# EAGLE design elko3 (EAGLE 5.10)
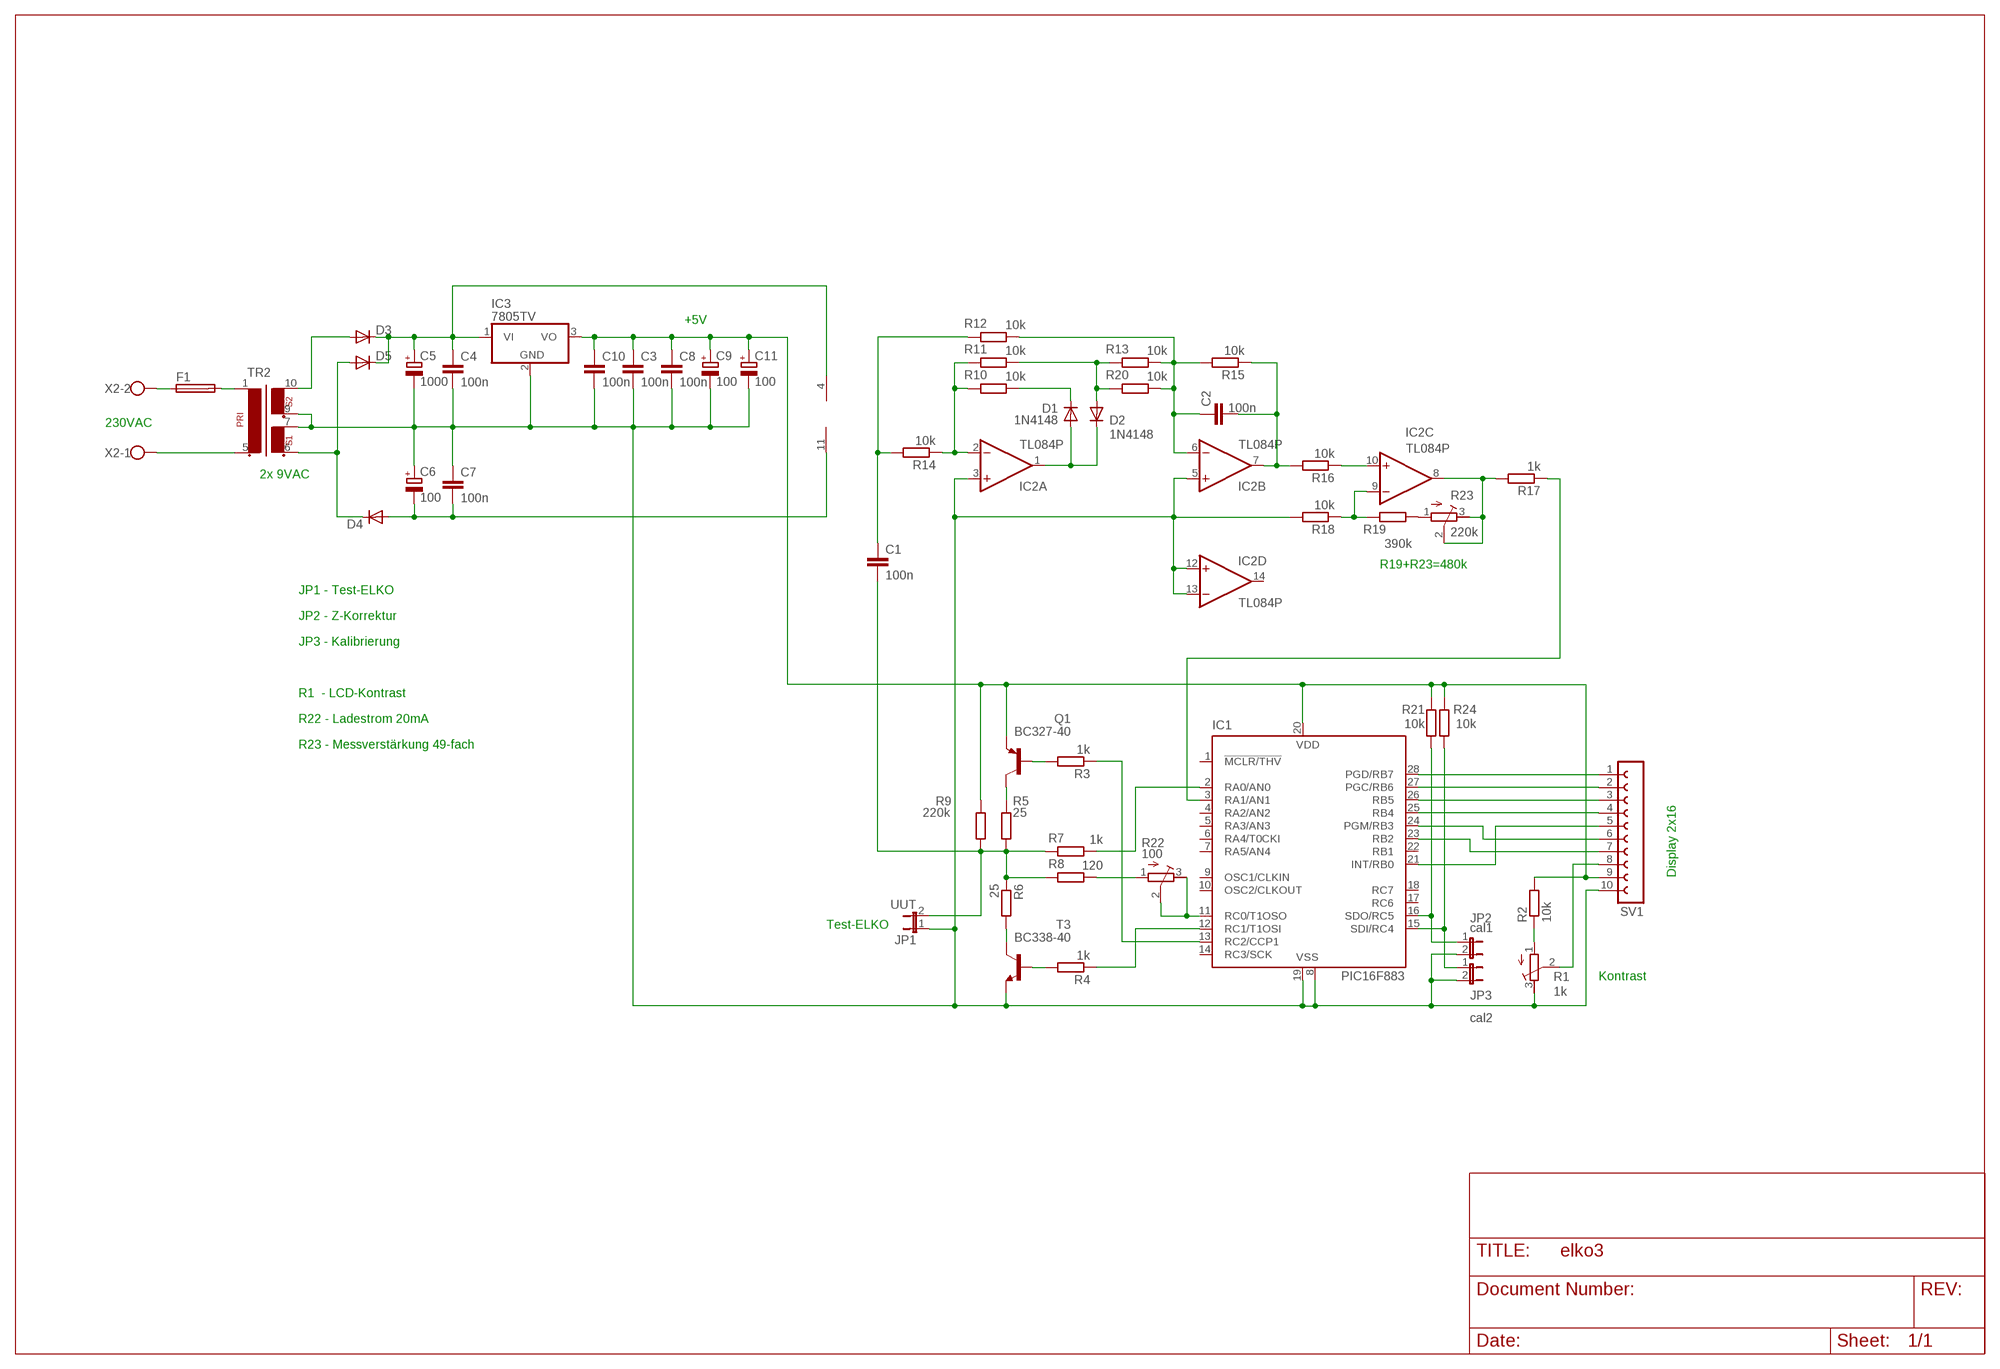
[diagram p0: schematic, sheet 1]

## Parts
C1  100n  C-EU050-025X075  [C050-025X075]
C2  100n  C-EU050-025X075  [C050-025X075]
C3  100n  C-EU050-025X075  [C050-025X075]
C4  100n  C-EU050-025X075  [C050-025X075]
C5  1000  CPOL-EUE5-8.5  [E5-8,5]
C6  100  CPOL-EUE5-6  [E5-6]
C7  100n  C-EU050-025X075  [C050-025X075]
C8  100n  C-EU050-025X075  [C050-025X075]
C9  100  CPOL-EUE5-6  [E5-6]
C10  100n  C-EU050-025X075  [C050-025X075]
C11  100  CPOL-EUE5-6  [E5-6]
D1  1N4148  1N4148DO35-7  [DO35-7]
D2  1N4148  1N4148DO35-7  [DO35-7]
D3  DIODE-DO15-12  [DO15-12]
D4  DIODE-DO15-12  [DO15-12]
D5  DIODE-DO15-12  [DO15-12]
F1  19560  [19560]
IC1  PIC16F883  PIC16873P  [DIL28-3]
IC2  TL084P  [DIL14]
IC3  7805TV  [TO220V]
JP1  UUT  JP1E  [JP1]
JP2  cal1  JP1E  [JP1]
JP3  cal2  JP1E  [JP1]
Q1  BC327-40  [TO92-EBC]
R1  1k  R-TRIMM3339P  [RTRIM3339P]
R2  10k  R-EU_0207/10  [0207/10]
R3  1k  R-EU_0207/10  [0207/10]
R4  1k  R-EU_0207/10  [0207/10]
R5  25  R-EU_0207/10  [0207/10]
R6  25  R-EU_0207/10  [0207/10]
R7  1k  R-EU_0207/10  [0207/10]
R8  120  R-EU_0207/10  [0207/10]
R9  220k  R-EU_0207/10  [0207/10]
R10  10k  R-EU_0207/10  [0207/10]
R11  10k  R-EU_0207/10  [0207/10]
R12  10k  R-EU_0207/10  [0207/10]
R13  10k  R-EU_0207/10  [0207/10]
R14  10k  R-EU_0207/10  [0207/10]
R15  10k  R-EU_0207/10  [0207/10]
R16  10k  R-EU_0207/10  [0207/10]
R17  1k  R-EU_0207/10  [0207/10]
R18  10k  R-EU_0207/10  [0207/10]
R19  390k  R-EU_0207/10  [0207/10]
R20  10k  R-EU_0207/10  [0207/10]
R21  10k  R-EU_0207/10  [0207/10]
R22  100  R-TRIMM64W  [RTRIM64W]
R23  220k  R-TRIMM64W  [RTRIM64W]
R24  10k  R-EU_0207/10  [0207/10]
SV1  FE10-1  [FE10]
T3  BC338-40  NPNBC338-40TO92-EBC  [TO92-EBC]
TR2  VV12  [VV12]
X2  W237-102  [W237-102]

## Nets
N$1: IC1.28(PGD/RB7) SV1.1
N$2: IC1.27(PGC/RB6) SV1.2
N$3: IC1.26(RB5) SV1.3
N$4: IC1.25(RB4) SV1.4
N$5: IC1.21(INT/RB0) SV1.5
N$6: IC1.24(PGM/RB3) SV1.6
N$7: IC1.23(RB2) SV1.7
N$8: R19.1 R23.1(E)
N$9: R8.1 R22.1(E)
N$10: C3.1 C8.1 C9.+ C10.1 C11.+ IC1.20(VDD) IC3.3(VO) Q1.E R2.2 R9.1 R21.2 R24.2 SV1.9
N$11: R1.2(S) SV1.8
N$12: C1.2 JP1.2 R5.2 R6.1 R7.2 R8.2 R9.2
N$13: IC1.2(RA0/AN0) R7.1
N$14: IC1.11(RC0/T1OSO) R22.2(S) R22.3(A)
N$15: Q1.C R5.1
N$16: Q1.B R3.2
N$17: R4.2 T3.B
N$18: IC1.12(RC1/T1OSI) R4.1
N$19: IC1.13(RC2/CCP1) R3.1
N$20: C4.1 C5.+ D3.C D5.C IC2.4(P:V+) IC3.1(VI)
N$21: IC2.2(A:-IN) R10.2 R11.2 R14.1
N$22: D1.A D2.C IC2.1(A:OUT)
N$23: R1.1(E) R2.1
N$24: D1.C R10.1
N$25: D2.A R11.1 R13.2 R20.2
N$26: C1.1 R12.2 R14.2
N$27: C2.1 IC2.6(B:-IN) R12.1 R13.1 R15.2 R20.1
N$28: IC1.16(SDO/RC5) JP2.1 R21.1
N$29: C2.2 IC2.7(B:OUT) R15.1 R16.2
N$30: IC2.10(C:+IN) R16.1
N$31: IC2.8(C:OUT) R17.2 R23.2(S) R23.3(A)
N$32: IC2.9(C:-IN) R18.1 R19.2
N$33: IC1.3(RA1/AN1) R17.1
N$34: R6.2 T3.C
N$35: IC1.15(SDI/RC4) JP3.1 R24.1
N$36: F1.1 X2.2
N$37: C6.- C7.2 D4.A IC2.11(P:V-)
N$38: D4.C D5.A TR2.6
N$39: F1.2 TR2.1
N$40: TR2.5 X2.1
N$41: D3.A TR2.10
VSS: C3.2 C4.2 C5.- C6.+ C7.1 C8.2 C9.- C10.2 C11.- IC1.8(VSS) IC1.19(VSS) IC2.3(A:+IN) IC2.5(B:+IN) IC2.12(D:+IN) IC2.13(D:-IN) IC3.2(GND) JP1.1 JP2.2 JP3.2 R1.3(A) R18.2 SV1.10 T3.E TR2.7 TR2.9
Unconnected: IC1.1(!MCLR/THV) IC1.4(RA2/AN2) IC1.5(RA3/AN3) IC1.6(RA4/T0CKI) IC1.7(RA5/AN4) IC1.9(OSC1/CLKIN) IC1.10(OSC2/CLKOUT) IC1.14(RC3/SCK) IC1.17(RC6) IC1.18(RC7) IC1.22(RB1) IC2.14(D:OUT)

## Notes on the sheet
- +5V
- 230VAC
- 2x 9VAC
- R19+R23=480k
- JP1 - Test-ELKO
- JP2 - Z-Korrektur
- JP3 - Kalibrierung
- R1  - LCD-Kontrast
- R22 - Ladestrom 20mA
- R23 - Messverstärkung 49-fach
- Display 2x16
- Test-ELKO
- Kontrast

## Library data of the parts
C1-C4 C7 C8 C10 = rcl:C-EU: CAPACITOR, European symbol
C5 C6 C9 C11 = rcl:CPOL-EU: POLARIZED CAPACITOR, European symbol
D1 D2 = diode:1N4148: DIODE
D3-D5 = diode:DIODE-: DIODE
F1 = fuse:19560: FUSE HOLDER
IC1 = microchip-6:PIC16*873: MICROCONTROLLER flash type
IC2 = linear:TL084: OP AMP
IC3 = linear:78*: Positive VOLTAGE REGULATOR Source: http://cache.national.com/ds/LM/LM78L05.pdf http://www.fairchildsemi.com/ds/LM/LM7805.pdf
JP1-JP3 = jumper:JP1E: JUMPER
Q1 = transistor-pnp:BC327*: PNP Transistror
R1 R22 R23 = rcl:R-TRIMM: Trimm resistor
R2-R21 R24 = rcl:R-EU_: RESISTOR, European symbol
SV1 = con-lsta:FE10-1: FEMALE HEADER
T3 = sprut:NPN: NPN Transistror
TR2 = trafo:VV12: TRANSFORMER 1 primary winding, 2 secondary windings BLOCK
X2 = con-wago-500:W237-102: WAGO SCREW CLAMP

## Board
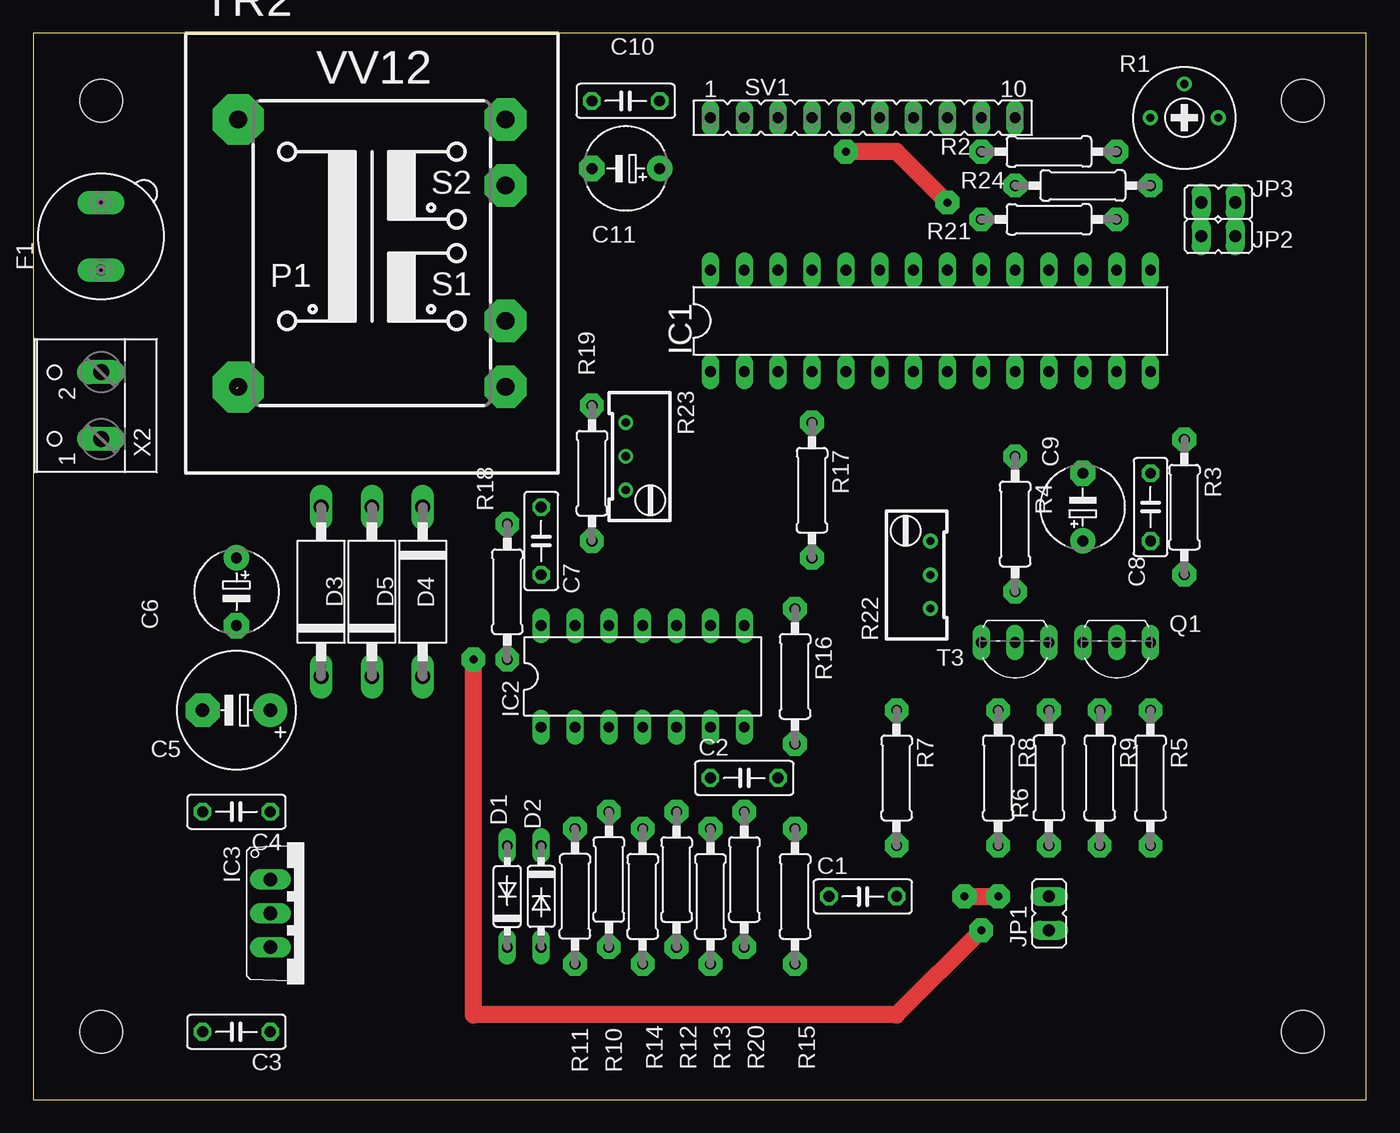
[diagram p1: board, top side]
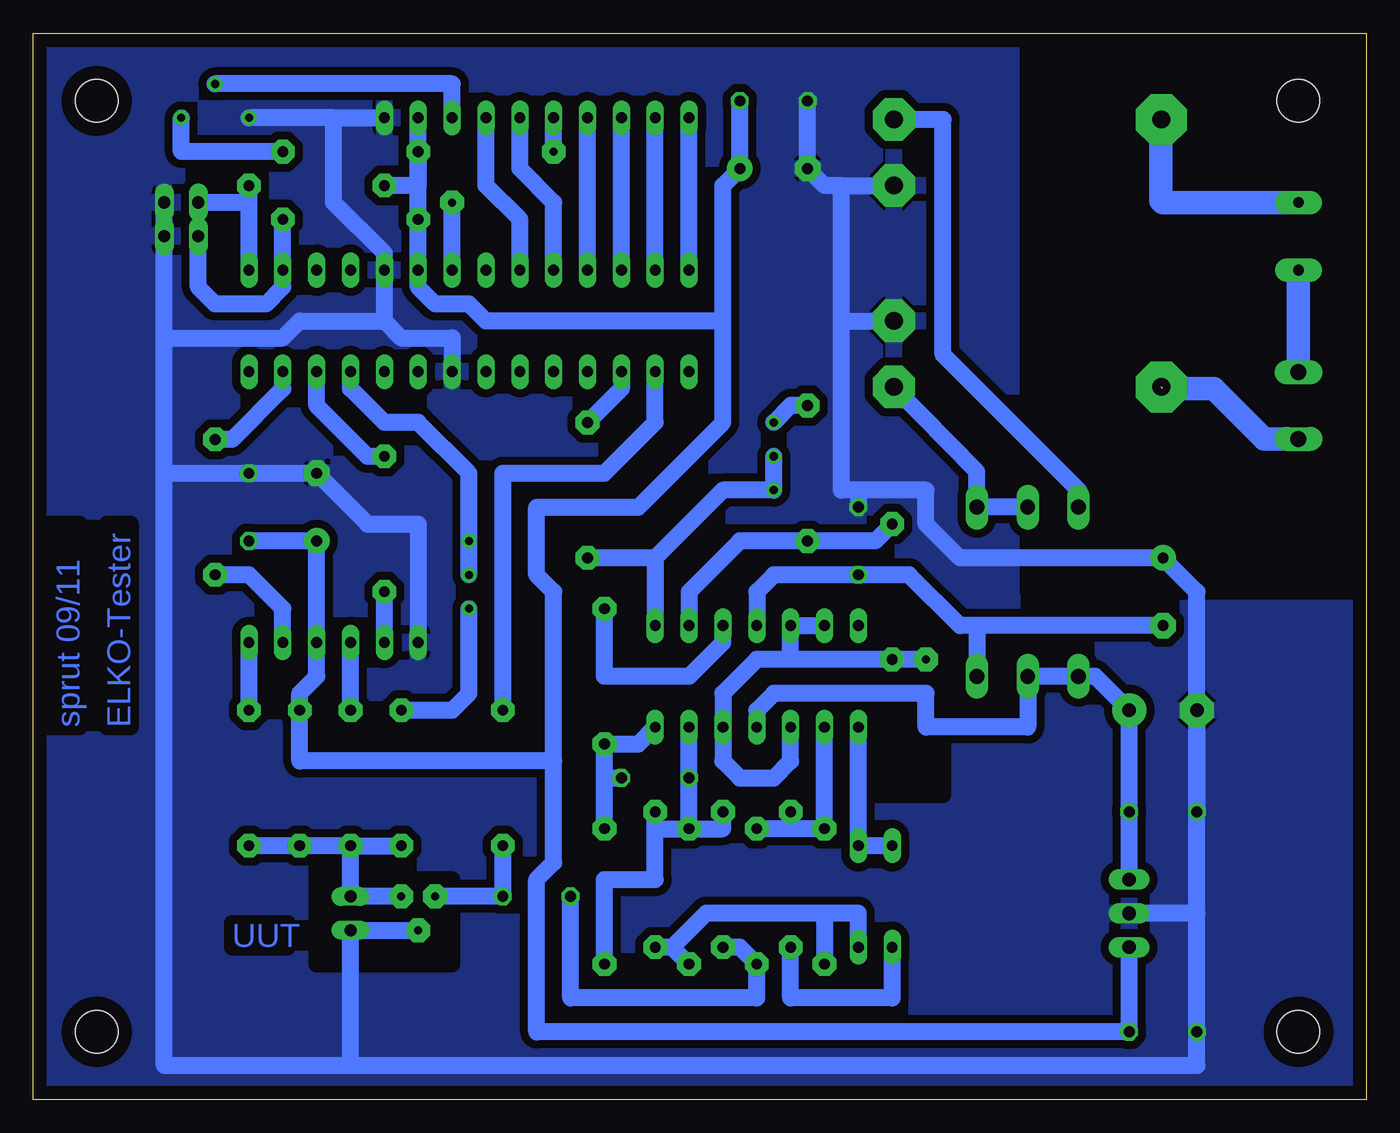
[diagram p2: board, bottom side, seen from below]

Size 100 x 80 mm. Coordinates in mm from the lower left corner, seen from the top.
Outline: 0,0 100,0 100,80 0,80 0,0
Copper layers (1*16): Top 0.035mm / dielectric 1.5mm / Bottom 0.035mm
Design rules "default": minimum track width 10mil, minimum drill 24mil, track to track 8mil, track to pad 8mil, pad to pad 8mil, via to via 8mil, smd to smd 8mil, copper to edge 40mil, drill to drill 8mil, minimum pad ring 10mil, minimum via ring 8mil, stop-mask expansion 4mil, vias tented up to drill 0mil, thermal gap 10mil
Holes 3.2 mm at 5.08,74.93 95.25,74.93 5.08,5.08 95.25,5.08
bRestrict: area 68.6,10.2 to 78.7,16.5; area 31.8,22.9 to 50.8,36.8; area 0,38.1 to 25.4,80

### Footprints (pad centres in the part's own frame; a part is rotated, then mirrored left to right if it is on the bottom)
C050-025X075 = drill 0.813 octagon: 1 -2.54,0; 2 2.54,0
E5-8,5 = drill 1.016 pad 2.54 round: + -2.54,0 | drill 1.016 pad 2.54 octagon: - 2.54,0
E5-6 = drill 0.813 pad 1.905 round: + -2.54,0 | drill 0.813 pad 1.905 octagon: - 2.54,0
DO35-7 = drill 0.813 long: A 3.81,0; C -3.81,0
DO15-12 = drill 1.118 long: A 6.35,0; C -6.35,0
19560 = drill 0.813 pad 1.778 long: 1 -2.54,0; 2 2.54,0
DIL28-3 = drill 0.813 long: 1 -16.51,-3.81; 2 -13.97,-3.81; 3 -11.43,-3.81; 4 -8.89,-3.81; 5 -6.35,-3.81; 6 -3.81,-3.81; 7 -1.27,-3.81; 8 1.27,-3.81; 9 3.81,-3.81; 10 6.35,-3.81; 11 8.89,-3.81; 12 11.43,-3.81; 13 13.97,-3.81; 14 16.51,-3.81; 15 16.51,3.81; 16 13.97,3.81; 17 11.43,3.81; 18 8.89,3.81; 19 6.35,3.81; 20 3.81,3.81; 21 1.27,3.81; 22 -1.27,3.81; 23 -3.81,3.81; 24 -6.35,3.81; 25 -8.89,3.81; 26 -11.43,3.81; 27 -13.97,3.81; 28 -16.51,3.81
DIL14 = drill 0.813 long: 1 -7.62,-3.81; 2 -5.08,-3.81; 3 -2.54,-3.81; 4 0,-3.81; 5 2.54,-3.81; 6 5.08,-3.81; 7 7.62,-3.81; 8 7.62,3.81; 9 5.08,3.81; 10 2.54,3.81; 11 0,3.81; 12 -2.54,3.81; 13 -5.08,3.81; 14 -7.62,3.81
TO220V = drill 1.016 long: 1 -2.54,-2.54; 2 0,-2.54; 3 2.54,-2.54
JP1 = drill 0.914 long: 1 0,-1.27; 2 0,1.27
TO92-EBC = drill 0.813 long: B 0,-1.27; C -2.54,-1.27; E 2.54,-1.27
RTRIM3339P = drill 0.61 round: 1 -2.54,0; 2 0,-2.54; 3 2.54,0
0207/10 = drill 0.813 pad 1.778 octagon: 1 -5.08,0; 2 5.08,0
RTRIM64W = drill 0.61 round: 1 1.27,-2.54; 2 1.27,0; 3 1.27,2.54
FE10 = drill 0.813 long: 1 -11.43,0; 2 -8.89,0; 3 -6.35,0; 4 -3.81,0; 5 -1.27,0; 6 1.27,0; 7 3.81,0; 8 6.35,0; 9 8.89,0; 10 11.43,0
VV12 = drill 1.321 pad 3.81 octagon: 1 -10.033,10.033; 5 -10.033,-10.033 | drill 1.321 pad 3.175 octagon: 6 10.033,-10.033; 7 10.033,-5.08; 9 10.033,5.08; 10 10.033,10.033
W237-102 = drill 1.194 long: 1 -2.5,-1.27; 2 2.5,-1.27

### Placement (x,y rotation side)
C1  62.23,15.24 0 top
C2  53.34,24.13 0 top
C3  15.24,5.08 180 top
C4  15.24,21.59 180 top
C5  15.24,29.21 180 top
C6  15.24,38.1 270 top
C7  38.1,41.91 270 top
C8  83.82,44.45 90 top
C9  78.74,44.45 90 top
C10  44.45,74.93 180 top
C11  44.45,69.85 180 top
D1  35.56,15.24 90 top
D2  38.1,15.24 270 top
D3  21.59,38.1 90 top
D4  29.21,38.1 270 top
D5  25.4,38.1 90 top
F1  5.08,64.77 90 top
IC1  67.31,58.42 0 top
IC2  45.72,31.75 0 top
IC3  20.32,13.97 270 top
JP1  76.2,13.97 0 top
JP2  88.9,64.77 270 top
JP3  88.9,67.31 270 top
Q1  81.28,33.02 180 top
R1  86.36,73.66 180 top
R2  76.2,71.12 180 top
R3  86.36,44.45 270 top
R4  73.66,43.18 270 top
R5  83.82,24.13 270 top
R6  76.2,24.13 90 top
R7  64.77,24.13 270 top
R8  72.39,24.13 270 top
R9  80.01,24.13 270 top
R10  43.18,16.51 90 top
R11  40.64,15.24 90 top
R12  48.26,16.51 270 top
R13  50.8,15.24 270 top
R14  45.72,15.24 270 top
R15  57.15,15.24 270 top
R16  57.15,31.75 270 top
R17  58.42,45.72 270 top
R18  35.56,38.1 270 top
R19  41.91,46.99 270 top
R20  53.34,16.51 270 top
R21  76.2,66.04 180 top
R22  66.04,39.37 0 top
R23  45.72,48.26 180 top
R24  78.74,68.58 180 top
SV1  62.23,73.66 0 top
T3  73.66,33.02 180 top
TR2  25.4,63.5 0 top
X2  3.81,52.07 90 top

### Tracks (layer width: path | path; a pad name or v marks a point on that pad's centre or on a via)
N$1
  Bottom 1.27: IC1.28 SV1.1
N$2
  Bottom 1.27: IC1.27 SV1.2
N$3
  Bottom 1.27: IC1.26 SV1.3
N$4
  Bottom 1.27: IC1.25 SV1.4
N$5  (via drill 0.6 pad 1.78)
  Top 1.27: v60.96,71.12 64.77,71.12 v68.58,67.31
  Bottom 1.27: v60.96,71.12 SV1.5 | IC1.21 v68.58,67.31
N$6
  Bottom 1.27: SV1.6 63.5,69.85 60.96,67.31 IC1.24
N$7
  Bottom 1.27: SV1.7 66.04,68.58 63.5,66.04 IC1.23
N$8
  Bottom 1.27: R19.1 43.18,52.07 R23.1
N$9
  Bottom 1.27: R8.1 68.58,29.21 67.31,30.48 R22.1
N$10
  Bottom 1.27: R2.2 SV1.9 | 60.96,25.4 80.01,25.4 R9.1 80.01,30.48 78.74,31.75 Q1.E C9.+ C8.1 | IC3.3 C3.1 62.23,5.08 62.23,16.51 60.96,17.78 60.96,25.4 | 48.26,58.42 66.04,58.42 67.31,59.69 69.85,59.69 71.12,60.96 IC1.20 R21.2 R2.2 | 48.26,58.42 48.26,50.8 54.61,44.45 62.23,44.45 62.23,39.37 60.96,38.1 60.96,25.4 | R2.2 71.12,68.58 R24.2 | 48.26,58.42 48.26,68.58 C11.+ C10.1
N$11
  Bottom 1.27: SV1.8 68.58,76.2 R1.2
N$12  (via drill 0.6 pad 1.78)
  Top 1.27: v69.85,15.24 v72.39,15.24
  Bottom 1.27: R6.1 R5.2 | R6.1 R9.2 | R6.1 JP1.2 v72.39,15.24 | R6.1 R8.2 | R7.2 C1.2 v69.85,15.24
N$13
  Bottom 1.27: IC1.2 53.34,50.8 57.15,46.99 64.77,46.99 R7.1
N$14
  Bottom 1.27: IC1.11 76.2,53.34 73.66,50.8 71.12,50.8 67.31,46.99 R22.3 R22.2
N$15
  Bottom 1.27: R5.1 Q1.C
N$16
  Bottom 1.27: R3.2 83.82,39.37 81.28,36.83 Q1.B
N$17
  Bottom 1.27: T3.B R4.2
N$18
  Bottom 1.27: IC1.12 78.74,52.07 74.93,48.26 R4.1
N$19
  Bottom 1.27: R3.1 85.09,49.53 81.28,53.34 IC1.13
N$20
  Bottom 1.27: IC3.1 C4.1 C5.+ 20.32,31.75 D3.C D5.C 25.4,27.94 33.02,27.94 33.02,30.48 44.45,30.48 45.72,29.21 IC2.4
N$21
  Bottom 1.27: 43.18,20.32 R11.2 IC2.2 | 43.18,20.32 R14.1 | 43.18,20.32 R10.2
N$22
  Bottom 1.27: IC2.1 D2.C D1.A
N$23
  Bottom 1.27: R1.1 88.9,71.12 R2.1
N$24
  Bottom 1.27: R10.1 43.18,7.62 35.56,7.62 D1.C
N$25
  Bottom 1.27: 52.07,11.43 R20.2 | 52.07,11.43 R13.2 | D2.A 38.1,13.97 40.64,13.97 | 40.64,13.97 49.53,13.97 52.07,11.43 | 40.64,13.97 R11.1
N$26
  Bottom 1.27: R12.2 46.99,11.43 R14.2 45.72,7.62 59.69,7.62 C1.1
N$27
  Bottom 1.27: R12.1 48.26,20.32 R13.1 | 53.34,20.32 R13.1 | 53.34,20.32 R20.1 | IC2.6 C2.1 R13.1 | R15.2 57.15,16.51 53.34,16.51 53.34,20.32
N$28
  Bottom 1.27: R21.1 IC1.16 81.28,60.96 82.55,59.69 86.36,59.69 87.63,60.96 JP2.1
N$29
  Bottom 1.27: IC2.7 54.61,26.67 R16.2 57.15,24.13 | R15.1 57.15,24.13 | 57.15,24.13 C2.2
N$30
  Bottom 1.27: IC2.10 48.26,34.29 50.8,31.75 57.15,31.75 R16.1
N$31
  Bottom 1.27: 53.34,40.64 IC2.8 | 53.34,40.64 R17.2 | R23.2 R23.3 48.26,45.72 53.34,40.64
N$32
  Bottom 1.27: IC2.9 50.8,38.1 46.99,41.91 R19.2 36.83,41.91 R18.1
N$33
  Bottom 1.27: R17.1 55.88,53.34 IC1.3
N$34
  Bottom 1.27: R6.2 T3.C
N$35
  Bottom 1.27: IC1.15 83.82,67.31 | 83.82,67.31 R24.1 | 83.82,67.31 JP3.1
N$36
  Bottom 1.778: X2.2 F1.1
N$37
  Bottom 1.27: IC2.11 45.72,38.1 44.45,39.37 C7.2 34.29,39.37 30.48,35.56 29.21,35.56 | C6.- 29.21,35.56 | 29.21,35.56 D4.A
N$38
  Bottom 1.27: D5.A D4.C 29.21,47.12 TR2.6
N$39
  Bottom 1.27: 15.24,67.31 15.39,67.46 | 15.39,73.51 TR2.1
  Bottom 1.778: F1.2 15.24,67.31 | 15.39,67.46 15.39,73.51
N$40  (1 unrouted)
  Bottom 1.778: X2.1 7.66,49.57 11.43,53.34 15.24,53.34
N$41
  Bottom 1.27: TR2.10 31.75,73.53 31.75,55.88 21.59,45.72 D3.A
VSS  (via drill 0.6 pad 1.78)
  Top 1.27: v33.02,33.02 33.02,6.35 64.77,6.35 v71.12,12.7
  Bottom 1.27: IC2.13 IC2.12 43.18,33.02 | 43.18,33.02 45.72,33.02 48.26,30.48 IC2.5 48.26,25.4 46.99,24.13 44.45,24.13 43.18,25.4 IC2.3 | 77.47,73.66 77.47,67.31 73.66,63.5 IC1.19 73.66,58.42 | 77.47,73.66 SV1.10 | 77.47,73.66 R1.3 | C5.- 12.7,38.1 C6.+ 30.48,40.64 33.02,43.18 33.02,45.72 38.1,45.72 | C5.- C4.2 | 12.7,13.97 C5.- | 12.7,13.97 IC3.2 | 12.7,13.97 C3.2 12.7,2.54 76.2,2.54 | 76.2,2.54 90.17,2.54 90.17,46.99 | 90.17,46.99 C8.2 C9.- 74.93,43.18 71.12,43.18 T3.E | 76.2,2.54 JP1.1 v71.12,12.7 | IC1.8 68.58,57.15 72.39,57.15 73.66,58.42 | 90.17,57.15 81.28,57.15 80.01,58.42 73.66,58.42 | 43.18,33.02 R18.2 v33.02,33.02 | JP3.2 JP2.2 90.17,57.15 | 90.17,46.99 90.17,57.15 | C10.2 C11.- 40.64,68.58 39.37,68.58 | 38.1,45.72 C7.1 | 39.37,68.58 TR2.9 | 39.37,58.42 39.37,45.72 38.1,45.72 | 39.37,58.42 TR2.7 | 39.37,58.42 39.37,68.58
  pour Bottom (isolate 0.61): 0,81.28 101.6,81.28 101.6,-1.27 -1.27,-1.27 -1.27,81.28

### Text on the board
Bottom: ELKO-Tester | sprut 09/11 | UUT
